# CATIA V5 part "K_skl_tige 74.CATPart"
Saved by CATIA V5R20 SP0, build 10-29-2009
Part number: skl_tige 74
Publications: "longueur verin commande", "longueur axe pivot", "liaison 21/74 sur 74", "droite appui verin commande", "Plan.-55", "Droite.1", "Droite.3"
Bounding box of the stored display mesh (mm): x -205 to -55, y -493.145 to 115, z 500 to 664.498
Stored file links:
  G:\Khaled_CFAO_2011\SIL\SIL_GR2\mdardier\Khaled\CAD_ThinkMOTION\K_skl_tige 74.CATPart
  G:\Khaled_CFAO_2011\SIL\SIL_GR2\mdardier\Khaled\CAD_ThinkMOTION\K_skl_ass_tandem.CATProduct
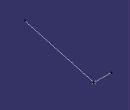
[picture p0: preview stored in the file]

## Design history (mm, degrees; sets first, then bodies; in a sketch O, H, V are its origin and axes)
External parameters (linked from other documents)
  `External.longueur verin commande` = 620 mm
  `External.longueur axe pivot` = 150 mm
Set1
  Point1 "liaison 21/74 sur 74": linked copy from another document
  Line1 "droite appui verin commande": linked copy from another document
  Plane1 "Plan.-55": linked copy from another document
Set2
  Line2: type PtDir, RefPoint Point1, Direction Line1, Start 0, End 630 {= `External.longueur verin commande` +0.01}
  Line3: type Normal, RefPoint Point1, RefSkin Plane1, Start 0, End 150 {= `External.longueur axe pivot`}
Body1 (main body)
